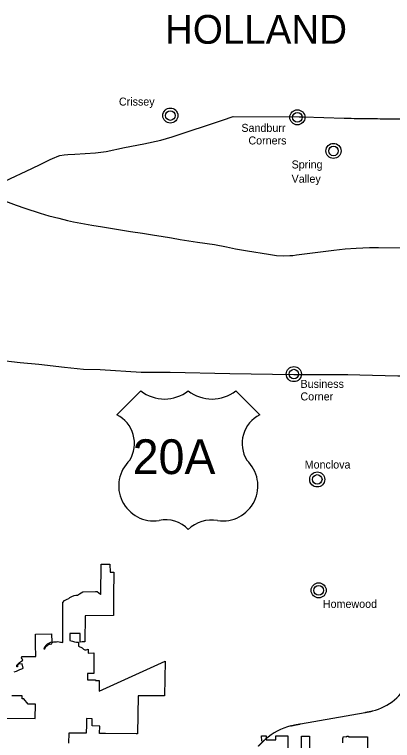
# Model space of a CAD drawing. Extents: x 0 to 750, y 0 to 507.
# Drawn here: x 180.7 to 229.9, y 149.3 to 243.8 of the extents above; entities that cross this region are included whole.
import ezdxf

# ---------------------------------------------------------------- set-up
doc = ezdxf.new("R2010")
doc.units = 0
for name, color, linetype in [('DV_X_Corp_Line', 7, 'Continuous'), ('GM_X_Corporation_Text', 7, 'Continuous'), ('GM_X_Interstate_Route', 7, 'Continuous'), ('GM_X_State_Route', 7, 'Continuous'), ('GM_X_US_Route', 7, 'Continuous')]:
    doc.layers.add(name, color=color, linetype=linetype)

msp = doc.modelspace()

# ---------------------------------------------------------------- linework, layer by layer
at = {"layer": 'DV_X_Corp_Line'}
for points in [[(180.7, 158.218), (181.003, 158.344), (181.248, 158.446), (181.436, 158.524), (181.673, 158.623), (181.855, 158.699), (181.725, 159.288), (181.241, 159.214), (181.138, 159.091), (181.138, 158.903), (181.038, 158.903), (181.038, 159.108), (181.132, 159.176), (181.247, 159.326), (181.397, 159.466), (181.632, 159.64), (181.802, 159.74), (181.748, 159.915), (181.628, 160.081), (181.664, 160.226), (182.414, 160.226), (183.507, 160.227), (183.451, 161.811), (183.441, 162.121), (183.448, 163.16), (185.563, 163.197), (185.576, 162.105), (185.435, 162.071), (185.24, 161.99), (184.975, 161.822), (184.823, 161.684), (184.686, 161.495), (184.58, 161.352), (184.539, 161.247), (184.662, 161.222), (184.746, 161.439), (184.789, 161.517), (184.992, 161.665), (185.272, 161.824), (185.372, 161.873), (185.464, 161.857), (185.598, 161.897), (185.635, 162.054), (185.856, 162.158), (186.185, 162.156), (186.376, 162.181), (186.562, 162.159), (186.734, 162.118), (186.84, 162.094), (187.034, 162.056), (187.024, 162.386), (187.007, 165.526), (186.998, 167.268), (187.251, 167.539), (187.576, 167.684), (187.793, 167.792), (187.92, 167.901), (188.209, 168.064), (188.48, 168.172), (188.697, 168.208), (188.914, 168.208), (189.203, 168.407), (189.619, 168.659), (191.291, 168.707), (191.479, 168.684), (191.921, 168.366), (191.984, 168.298), (191.987, 172.263), (193.157, 172.267), (193.162, 171.191), (193.669, 171.191), (193.609, 168.117), (193.614, 165.571), (189.929, 165.546), (189.904, 162.13), (189.524, 162.128), (189.266, 162.115), (189.257, 163.231), (187.926, 163.221), (187.911, 162.327), (188.294, 162.223), (188.549, 162.146), (188.817, 162.115), (189.072, 162.115), (189.078, 161.559), (189.533, 161.361), (189.705, 161.183), (189.888, 161.104), (189.993, 161.092), (190.073, 161.091), (190.324, 161.167), (190.312, 160.678), (191.069, 160.718), (191.07, 158.029), (190.247, 158.028), (190.226, 157.197), (191.279, 157.198), (191.279, 157.091), (191.74, 157.091), (191.74, 155.713), (200.353, 159.627), (200.236, 155.093), (196.808, 155.111), (196.728, 150.169), (196.578, 150.172), (192.563, 150.216), (191.799, 150.225), (191.821, 151.155), (190.857, 151.188), (190.857, 152.136), (190.102, 152.15), (190.082, 151.353), (190.076, 150.244), (187.802, 150.269), (187.772, 148.957)], [(176.627, 152.196), (183.424, 152.184), (183.45, 154.032), (182.513, 154.015), (181.96, 154.723), (181.71, 154.718), (181.71, 155.093), (180.389, 155.093)], [(212.901, 149.215), (212.895, 149.917), (213.468, 149.916), (213.472, 149.377), (214.752, 149.381), (214.737, 149.926), (216.32, 149.913), (216.28, 146.516)], [(218.07, 148.203), (218.074, 149.881), (219.129, 149.861), (219.141, 148.21)], [(223.455, 148.989), (223.455, 149.541), (223.517, 149.672), (223.543, 149.8), (223.99, 149.794), (223.993, 149.87), (224.209, 149.865), (224.209, 149.791), (226.679, 149.758), (226.646, 146.356)]]:
    msp.add_lwpolyline(points, dxfattribs=at)
for centre, radius in [((201.012, 230.647), 0.982), ((201.012, 230.647), 0.623), ((217.546, 230.418), 0.982), ((217.546, 230.418), 0.623), ((222.242, 226.042), 0.982), ((222.242, 226.042), 0.623), ((217.088, 196.993), 0.982), ((217.088, 196.993), 0.623), ((220.128, 183.28), 0.982), ((220.128, 183.28), 0.623), ((220.318, 168.846), 0.982), ((220.318, 168.846), 0.623)]:
    msp.add_circle(centre, radius, dxfattribs=at)
at = {"layer": 'GM_X_Interstate_Route'}
for p, q in [((197.168, 194.818), (194.058, 191.708)), ((197.168, 194.818), (194.058, 191.708)), ((212.64, 191.708), (209.53, 194.818)), ((212.64, 191.708), (209.53, 194.818))]:
    msp.add_line(p, q, dxfattribs=at)
msp.add_lwpolyline([(178.346, 219.956), (180.932, 218.961), (182.055, 218.572), (184.052, 217.936), (185.21, 217.606), (186.485, 217.269), (187.638, 216.997), (188.416, 216.831), (190.781, 216.361), (192.177, 216.149), (194.001, 215.868), (195.824, 215.568), (197.394, 215.328), (198.699, 215.118), (200.097, 214.887), (200.905, 214.77), (201.175, 214.718), (202.291, 214.529), (204.53, 214.185), (206.764, 213.842), (208.334, 213.561), (209.494, 213.308), (211.05, 213.031), (213.789, 212.593), (214.827, 212.442), (215.75, 212.383), (216.545, 212.409), (216.935, 212.44), (217.416, 212.5), (219.157, 212.729), (222.297, 213.123), (223.743, 213.286), (225.189, 213.394), (226.916, 213.468), (228.091, 213.464), (231.52, 213.427)], dxfattribs=at)
for centre, radius, start, end in [((200.258, 198.747), 4.999, 231.81301, 308.18697), ((200.258, 198.747), 4.999, 231.81301, 308.18697), ((206.439, 198.747), 4.999, 231.81301, 308.18697), ((206.439, 198.747), 4.999, 231.81301, 308.18697), ((192.113, 187.954), 4.228, 329.11751, 62.61081), ((192.113, 187.954), 4.228, 329.11751, 62.61081), ((214.584, 187.954), 4.228, 117.38919, 210.88249), ((214.584, 187.954), 4.228, 117.38919, 210.88249), ((198.853, 182.448), 4.562, 133.00455, 278.72816), ((198.853, 182.448), 4.562, 133.00455, 278.72816), ((207.845, 182.448), 4.562, 261.27184, 46.99545), ((207.845, 182.448), 4.562, 261.27184, 46.99545), ((200.385, 173.946), 4.081, 43.41772, 101.87423), ((200.385, 173.946), 4.081, 43.41772, 101.87423), ((206.397, 173.675), 4.331, 79.96126, 134.74679), ((206.397, 173.675), 4.331, 79.96126, 134.74679)]:
    msp.add_arc(centre, radius, start, end, dxfattribs=at)
at = {"layer": 'GM_X_State_Route'}
for points in [[(186.2, 225.289), (186.294, 225.327), (186.639, 225.432), (187.174, 225.537), (187.653, 225.588), (188.584, 225.64), (189.905, 225.706), (191.282, 225.78), (192.658, 225.989), (195.061, 226.493), (197.57, 226.98), (199.793, 227.45), (201.266, 227.869), (207.926, 230.102), (209.039, 230.475)], [(209.039, 230.475), (209.06, 230.482), (209.198, 230.529), (217.765, 230.476)], [(217.765, 230.476), (218.175, 230.466)], [(218.175, 230.466), (218.326, 230.462), (223.641, 230.32), (224.536, 230.296), (224.941, 230.285)], [(224.941, 230.285), (225.211, 230.278), (227.394, 230.252)], [(227.394, 230.252), (227.651, 230.249), (227.916, 230.245)], [(227.916, 230.245), (227.968, 230.245), (228.314, 230.241), (228.738, 230.236), (229.332, 230.228)], [(229.332, 230.228), (229.451, 230.227), (230.404, 230.216), (231.154, 230.207), (232.743, 230.188)], [(178.893, 221.799), (179.058, 221.88), (179.49, 222.086), (182.98, 223.772), (184.146, 224.316), (185.376, 224.924), (185.957, 225.19), (186.2, 225.289)]]:
    msp.add_lwpolyline(points, dxfattribs=at)
at = {"layer": 'GM_X_US_Route'}
msp.add_line((217.938, 151.459), (226.36, 152.957), dxfattribs=at)
for points in [[(175.437, 199.108), (175.448, 199.108), (175.766, 199.096), (176.639, 199.04), (177.14, 199.007), (178.41, 198.855), (181.462, 198.499), (183.894, 198.271), (187.244, 197.911), (189.717, 197.621), (191.879, 197.576), (197.216, 197.253), (201.003, 197.247), (208.742, 197.09), (217.09, 196.951)], [(217.09, 196.951), (217.222, 196.949), (222.824, 196.937), (224.094, 196.934), (225.678, 196.897), (230.62, 196.785), (234.366, 196.758), (234.743, 196.756), (234.983, 196.754)]]:
    msp.add_lwpolyline(points, dxfattribs=at)
for centre, radius, start, end in [((225.597, 160.102), 7.162, 284.08609, 335.3259), ((218.758, 143.283), 8.185, 104.46109, 131.21971)]:
    msp.add_arc(centre, radius, start, end, dxfattribs=at)
for points in [[(226.36, 152.957), (226.374, 152.959), (226.387, 152.962), (226.4, 152.964), (226.413, 152.967), (226.427, 152.969), (226.44, 152.971), (226.453, 152.974), (226.467, 152.976), (226.48, 152.978), (226.493, 152.981), (226.507, 152.983), (226.52, 152.986), (226.533, 152.988), (226.546, 152.99), (226.56, 152.993), (226.573, 152.995), (226.586, 152.998), (226.6, 153), (226.613, 153.002), (226.626, 153.005), (226.64, 153.007), (226.653, 153.01), (226.666, 153.012), (226.679, 153.015), (226.693, 153.017), (226.706, 153.02), (226.719, 153.022), (226.733, 153.025), (226.746, 153.027), (226.759, 153.03), (226.772, 153.032), (226.786, 153.035), (226.799, 153.037), (226.812, 153.04), (226.825, 153.042), (226.839, 153.045), (226.852, 153.047), (226.865, 153.05), (226.878, 153.053), (226.892, 153.055), (226.905, 153.058), (226.918, 153.061), (226.931, 153.063), (226.945, 153.066), (226.958, 153.069), (226.971, 153.071), (226.984, 153.074), (226.998, 153.077), (227.011, 153.08), (227.024, 153.082), (227.037, 153.085), (227.051, 153.088), (227.064, 153.091), (227.077, 153.094), (227.09, 153.097), (227.103, 153.099), (227.117, 153.102), (227.13, 153.105), (227.143, 153.108), (227.156, 153.111), (227.169, 153.114), (227.183, 153.117), (227.196, 153.12), (227.209, 153.123), (227.222, 153.126), (227.235, 153.129), (227.248, 153.133), (227.261, 153.136), (227.275, 153.139), (227.288, 153.142), (227.301, 153.145), (227.314, 153.148), (227.327, 153.152), (227.34, 153.155)], [(216.714, 151.209), (216.73, 151.213), (216.747, 151.217), (216.763, 151.221), (216.779, 151.225), (216.796, 151.23), (216.812, 151.234), (216.829, 151.238), (216.845, 151.242), (216.861, 151.246), (216.878, 151.249), (216.894, 151.253), (216.911, 151.257), (216.927, 151.261), (216.944, 151.265), (216.96, 151.269), (216.977, 151.272), (216.993, 151.276), (217.01, 151.28), (217.026, 151.283), (217.043, 151.287), (217.059, 151.291), (217.076, 151.294), (217.092, 151.298), (217.109, 151.301), (217.125, 151.305), (217.142, 151.308), (217.158, 151.312), (217.175, 151.315), (217.191, 151.319), (217.208, 151.322), (217.224, 151.326), (217.241, 151.329), (217.257, 151.332), (217.274, 151.336), (217.291, 151.339), (217.307, 151.342), (217.324, 151.346), (217.34, 151.349), (217.357, 151.352), (217.373, 151.355), (217.39, 151.359), (217.407, 151.362), (217.423, 151.365), (217.44, 151.368), (217.456, 151.371), (217.473, 151.374), (217.49, 151.378), (217.506, 151.381), (217.523, 151.384), (217.539, 151.387), (217.556, 151.39), (217.573, 151.393), (217.589, 151.396), (217.606, 151.399), (217.622, 151.402), (217.639, 151.405), (217.656, 151.408), (217.672, 151.411), (217.689, 151.414), (217.705, 151.417), (217.722, 151.42), (217.739, 151.423), (217.755, 151.426), (217.772, 151.429), (217.789, 151.432), (217.805, 151.435), (217.822, 151.438), (217.839, 151.441), (217.855, 151.444), (217.872, 151.447), (217.888, 151.45), (217.905, 151.453), (217.922, 151.456), (217.938, 151.459)], [(212.467, 148.57), (212.479, 148.582), (212.491, 148.594), (212.503, 148.606), (212.515, 148.618), (212.527, 148.63), (212.538, 148.642), (212.55, 148.654), (212.562, 148.666), (212.574, 148.678), (212.586, 148.69), (212.598, 148.702), (212.609, 148.714), (212.621, 148.726), (212.633, 148.738), (212.645, 148.75), (212.657, 148.762), (212.669, 148.774), (212.681, 148.786), (212.692, 148.799), (212.704, 148.811), (212.716, 148.823), (212.728, 148.835), (212.74, 148.846), (212.752, 148.858), (212.764, 148.87), (212.776, 148.882), (212.788, 148.894), (212.8, 148.906), (212.812, 148.918), (212.824, 148.93), (212.836, 148.942), (212.848, 148.954), (212.86, 148.966), (212.872, 148.978), (212.884, 148.99), (212.896, 149.001), (212.908, 149.013), (212.92, 149.025), (212.932, 149.037), (212.944, 149.049), (212.956, 149.061), (212.968, 149.072), (212.98, 149.084), (212.992, 149.096), (213.004, 149.108), (213.017, 149.119), (213.029, 149.131), (213.041, 149.143), (213.053, 149.154), (213.065, 149.166), (213.078, 149.178), (213.09, 149.189), (213.102, 149.201), (213.114, 149.212), (213.127, 149.224), (213.139, 149.236), (213.151, 149.247), (213.164, 149.259), (213.176, 149.27), (213.189, 149.282), (213.201, 149.293), (213.213, 149.304), (213.226, 149.316), (213.238, 149.327), (213.251, 149.339), (213.263, 149.35), (213.276, 149.361), (213.289, 149.373), (213.301, 149.384), (213.314, 149.395), (213.326, 149.406), (213.339, 149.418), (213.352, 149.429), (213.364, 149.44)]]:
    msp.add_spline(points, degree=3, dxfattribs=at)

# ---------------------------------------------------------------- texts
at = {"layer": 'DV_X_Corp_Line'}
for s, p in [('Crissey', (194.32, 231.945)), ('Sandburr', (210.259, 228.523)), ('Corners', (211.172, 226.884)), ('Spring', (216.793, 223.76)), ('Valley', (216.793, 221.901)), ('Business', (217.948, 195.204)), ('Corner', (217.948, 193.565)), ('Monclova', (218.496, 184.698)), ('Homewood', (220.863, 166.56))]:
    msp.add_text(s, height=1.0417, rotation=0.00001, dxfattribs=at).set_placement(p)
at = {"layer": 'GM_X_Corporation_Text'}
msp.add_text('HOLLAND', height=3.7501, rotation=0.00001, dxfattribs=at).set_placement((200.319, 239.993))
at = {"layer": 'GM_X_Interstate_Route'}
msp.add_text('20A', height=4.5281, dxfattribs=at).set_placement((196.11, 183.975))

doc.saveas('drawing.dxf')
